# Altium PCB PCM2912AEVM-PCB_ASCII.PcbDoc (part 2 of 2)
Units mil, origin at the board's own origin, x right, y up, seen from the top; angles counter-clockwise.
Board outline 2362.2 x 944.88 mil, 4 copper layers (Top Layer, GND1 Layer, GND2 Layer, Bottom Layer), stack 58.906 mil thick; 73 components, 35 nets, 156 pads, 64 vias.
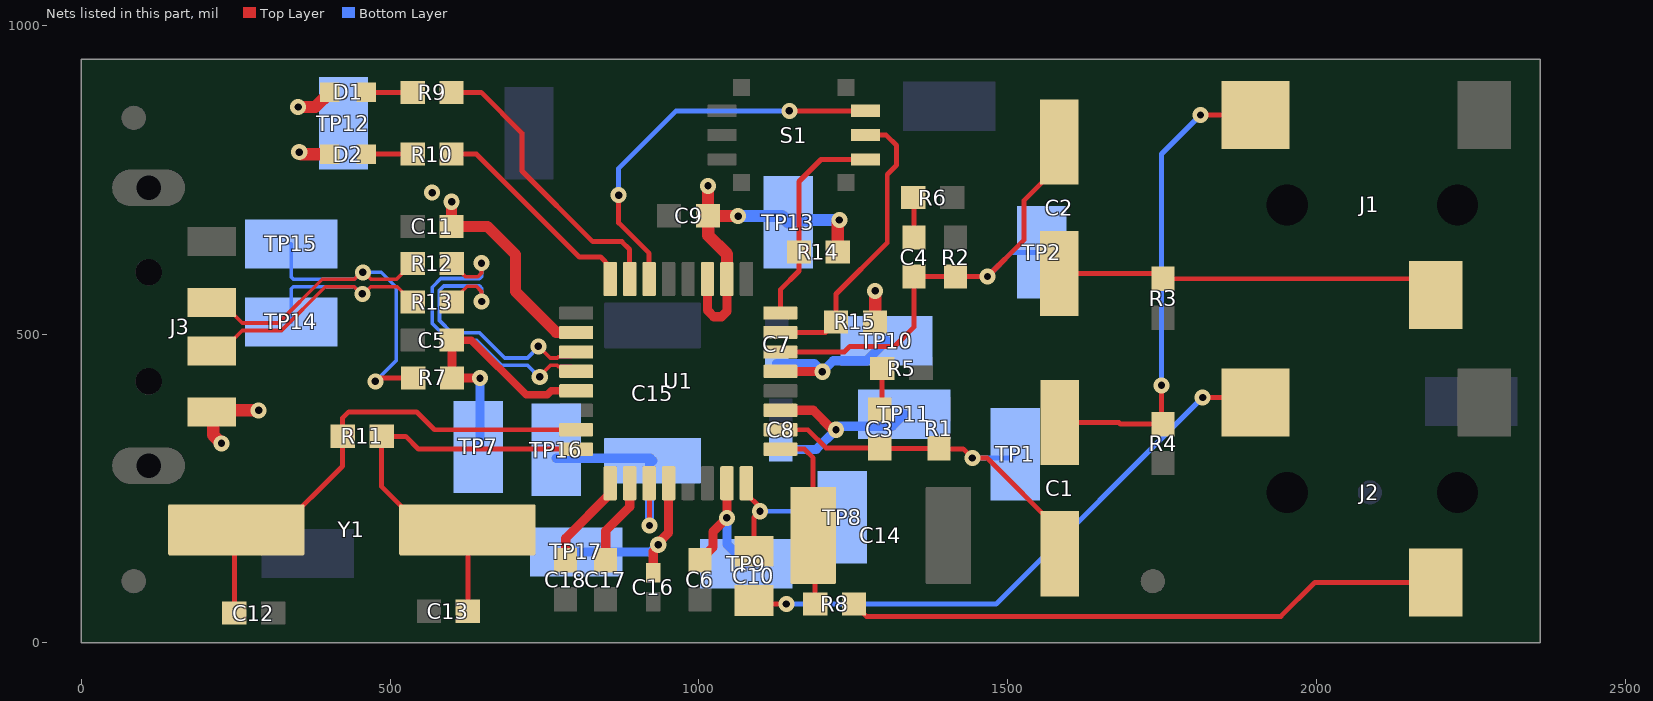
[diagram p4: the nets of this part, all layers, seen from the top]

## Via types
v1: diameter 26, hole 12, Top Layer to Bottom Layer, tented both sides, 64 vias

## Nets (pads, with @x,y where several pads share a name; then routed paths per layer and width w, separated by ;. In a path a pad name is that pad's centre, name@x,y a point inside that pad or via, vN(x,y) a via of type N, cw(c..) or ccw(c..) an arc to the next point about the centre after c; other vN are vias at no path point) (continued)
NetC1_1: C1.1 C3.1 R1.2 TP1.1 U1.18 | length 630.9
  Top Layer w8: U1.18@1132.02,345.06 1176.43,345.06 1205.82,315.67 1292.85,315.67 C3.1@1292.85,314.69 1388.41,314.69 R1.2@1388.75,315.03 1388.75,314.04 1428.07,314.04 v1(1442.77,299.34) 1466.62,299.34 1584.34,181.62 C1.1@1584.34,144.22
  Bottom Layer w8: v1(1442.77,299.34) 1506.27,299.34 TP1.1@1512.33,305.41
NetC1_2: C1.2 J1.2 R4.2 | length 785.7
  Top Layer w8: C1.2@1584.34,356.82 1680,356.82 1682.67,354.15 R4.2@1751.71,354.15 1749.05,356.82 v1(1749.05,416.8) ; v1(1812.19,854.74) J1.2@1901.57,854.74
  Bottom Layer w8: v1(1749.05,416.8) 1749.05,791.59 v1(1812.19,854.74)
NetC2_1: C2.1 C4.1 R2.2 TP2.1 U1.22 | length 803.3
  Top Layer w8: U1.22@1132.02,471.04 1235.53,471.04 1244.41,479.92 1316.72,479.92 1348.57,511.77 C4.1@1348.57,593.24 R2.2@1415.51,593.24 v1(1467.31,593.24) 1526.13,652.06 1526.13,716.07 1583.5,773.43 C2.1@1583.5,810.84
  Bottom Layer w8: v1(1467.31,593.24) 1506.41,632.34 TP2.1@1555.09,632.34
NetC2_2: C2.2 J1.3 R3.2 | length 623.8
  Top Layer w8: C2.2@1583.5,598.24 1742.98,598.24 R3.2@1751.71,589.5 2166.8,589.5 J1.3@2192.91,563.4
NetC3_2: C3.2 R5.2 | length 68
  Top Layer w8: C3.2@1292.85,377.68 1296.7,381.54 R5.2@1296.7,444.06
NetC4_2: C4.2 R6.2 | length 65.4
  Top Layer w8: R6.2@1347.08,721.03 1348.57,719.54 C4.2@1348.57,656.23
NetC5_1: C5.1 R7.2 TP7.1 U1.5 | length 460.7
  Top Layer w8: R7.2@599.79,429.51 R7.2@600.31,428.99 ; C5.1@599.79,490.22 C5.1@600.05,489.96 ; v1@645.29,429.02 v1(645.59,428.72)
  Top Layer w12: C5.1@599.79,490.22 631.65,490.22 720.21,401.67 754.32,401.67 760.71,408.05 U1.5@801.31,408.05
  Top Layer w15: R7.2@599.79,429.51 600.05,429.77 C5.1@600.05,489.96 ; R7.2@600.31,428.99 600.44,428.85 645.12,428.85 v1@645.29,429.02
  Bottom Layer w10: TP7.1@643.02,317.17 TP7.1@645.59,319.74
  Bottom Layer w15: TP7.1@645.59,319.74 v1(645.59,428.72)
NetC6_1: C6.1 TP9.1 U1.15 | length 230.1
  Top Layer w15: C6.1@1001.62,133.66 1022.78,154.83 1022.78,179.87 v1(1045.4,202.49) U1.15@1045.4,258.44
  Bottom Layer w15: v1(1045.4,202.49) 1045.4,159.86 TP9.1@1076.9,128.36
NetC7_1: C7.1 TP10.1 U1.21 | length 272.2
  Top Layer w15: U1.21@1132.02,439.54 1199.42,439.54 v1(1199.97,439)
  Bottom Layer w15: C7.1@1126.07,452.24 1186.72,452.24 v1(1199.97,439) 1217.64,456.68 1271.22,456.68 TP10.1@1303.82,489.27
NetC8_1: C8.1 TP11.1 U1.19 | length 326.8
  Top Layer w15: U1.19@1132.02,376.55 1184.97,376.55 1216.47,345.06 v1(1221.97,345.06)
  Bottom Layer w15: C8.1@1132.57,313.26 1190.17,313.26 v1(1221.97,345.06) 1227.64,350.72 1313.12,350.72 TP11.1@1332.71,370.31
NetC10_1: C10.1 TP8.1 U1.16 | length 260.8
  Top Layer w8: U1.16@1076.9,258.44 1076.9,241.71 1098.99,219.62 v1(1098.99,213.12) 1088.99,203.12 C10.1@1088.99,148.34
  Bottom Layer w8: v1(1098.99,213.12) 1222.64,213.12 TP8.1@1232.39,203.37
NetC10_2: C10.2 J2.2 | length 956.6
  Top Layer w8: C10.2@1088.99,68.34 1094.36,62.97 v1(1141.58,62.97) ; v1(1815.53,397.22) 1893.52,397.22 J2.2@1901.57,389.17
  Bottom Layer w8: v1(1141.58,62.97) 1481.27,62.97 v1(1815.53,397.22)
NetC12_2: C12.2 R11.1 U1.7 Y1.1 | length 823.3
  Top Layer w8: C12.2@247.83,48.04 247.83,179.87 Y1.1@251,183.05 319.9,183.05 423.28,286.43 R11.1@423.28,334.45 423.28,364.22 433.08,374.02 542.83,374.02 571.79,345.06 U1.7@801.31,345.06
NetC13_2: C13.2 R11.2 U1.8 Y1.2 | length 704.1
  Top Layer w8: R11.2@486.28,334.45 486.28,252.89 556.12,183.05 Y1.2@625.02,183.05 625.91,182.16 C13.2@625.91,51.2 ; R11.2@487.26,334.45 525.12,334.45 546.01,313.56 U1.8@801.31,313.56
NetC14_2: C14.2 R8.1 U1.17 | length 296.6
  Top Layer w8: U1.17@1132.02,313.56 1170.92,313.56 1184.97,299.51 C14.2@1184.97,174.18 1188.15,170.99 R8.1@1188.15,62.97
NetC15_2: C15.2 TP16.1 U1.11 | length 333.4
  Top Layer w8: U1.11@919.42,258.44 919.71,258.15 919.71,190.29 v1(920,190)
  Bottom Layer w15: TP16.1@769.07,298.91 921.17,298.91 C15.2@925.08,295 920,289.91 v1(920,190)
NetC16_1: C16.1 TP17.1 U1.12 | length 291.6
  Top Layer w15: C16.1@926.18,113.81 926.18,147.87 934.21,155.89 v1(934.21,158.87) ; v1@932.95,160.12 950.91,178.08 U1.12@950.91,258.44
  Bottom Layer w15: TP17.1@801.61,147.14 922.48,147.14 v1(934.21,158.87)
NetC17_1: C17.1 U1.10 | length 140.9
  Top Layer w15: C17.1@849.07,133.66 849.07,181.56 887.92,220.41 U1.10@887.92,258.44
NetC18_1: C18.1 U1.9 | length 154.7
  Top Layer w15: C18.1@784.21,133.66 784.21,169.5 856.43,241.71 U1.9@856.43,258.44
NetD1_2: D1.2 R9.1 | length 74.9
  Top Layer w8: D1.2@461.68,891.37 R9.1@536.58,891.37
NetD2_2: D2.2 R10.1 | length 74.9
  Top Layer w8: D2.2@461.68,791.37 R10.1@536.58,791.37
NetJ2_3: J2.3 R8.2 | length 972.7
  Top Layer w8: R8.2@1251.15,62.97 1271.11,43 1942.33,43 1997.16,97.83 J2.3@2192.9,97.83
NetJ3_2: J3.2 R13.1 TP14.1 | length 563.4
  Top Layer w6: J3.2@211.33,472.44 227.08,472.44 260.45,505.81 324.24,505.81 395.17,576.74 441.49,576.74 453.22,565 v1(455,565) 457.25,565 468.75,576.5 511.53,576.5 535.81,552.22 R13.1@536.79,552.22
  Bottom Layer w6: TP14.1@339.99,519.54 339.99,573.24 343.5,576.76 428.03,576.76 441.49,576.74 453.22,565 v1(455,565)
NetJ3_3: J3.3 R7.1 R12.1 TP15.1 | length 858.6
  Top Layer w6: J3.3@211.33,551.18 227.08,551.18 260.45,517.81 319.27,517.81 390.2,588.74 442.41,588.74 453.68,600 v1(455.93,600) 457.94,600 469.44,588.5 509.96,588.5 535.76,614.3 R12.1@536.74,614.3
  Top Layer w8: v1(476.04,423.31) 480.37,423.31 486.05,428.99 R7.1@537.31,428.99
  Bottom Layer w6: TP15.1@339.66,645.84 339.99,645.51 339.99,592.27 343.5,588.76 433,588.76 ; 433.02,588.74 442.41,588.74 453.68,600 v1(455.93,600) 485.56,600 509.96,575.6 509.96,457.23 v1(476.04,423.31)
NetR9_2: R9.2 U1.31 | length 477.4
  Top Layer w8: R9.2@599.57,891.37 647.63,891.37 713.68,825.32 713.68,764.08 828.16,649.61 875.19,649.61 887.92,636.88 U1.31@887.92,589.15
NetR10_2: R10.2 U1.32 | length 352.4
  Top Layer w8: R10.2@599.57,791.37 639.84,791.37 806.48,624.74 840.94,624.74 856.43,609.25 U1.32@856.43,589.15
NetR12_2: R12.2 U1.4 | length 525.1
  Top Layer w6: R12.2@599.73,614.3 600.72,614.3 622.23,592.79 642.16,592.79 648.04,598.66 v1(648.04,614.84) ; v1(742.31,430.67) 742.31,432.11 759.49,449.29 770.25,449.29 772.18,447.37 793.48,447.37 U1.4@801.31,439.54
  Bottom Layer w6: v1@648.07,614.82 648.07,593.32 644.55,589.8 582.01,589.8 568.1,575.89 568.1,516.94 594.95,490.09 639.81,490.09 680.56,449.33 722.49,449.33 741.16,430.67 v1(742.31,430.67)
NetR13_2: R13.2 U1.3 | length 487.7
  Top Layer w6: R13.2@599.79,552.22 599.92,552.22 624.96,577.26 639.9,577.26 648.09,569.07 v1(648.09,552.76) ; v1(740,480) 740.78,480 759.49,461.29 770.25,461.29 772.18,463.21 793.48,463.21 U1.3@801.31,471.04
  Bottom Layer w6: v1(648.09,552.76) 648.07,574.29 644.55,577.8 586.98,577.8 580.1,570.92 580.1,521.91 599.92,502.09 644.78,502.09 685.53,461.33 722.49,461.33 740,478.84 v1(740,480)
NetR14_1: R14.1 S1.4 U1.24 | length 348.1
  Top Layer w8: U1.24@1132.02,534.03 1132.02,572.01 1162.07,602.06 R14.1@1162.07,632.76 1162.07,747.07 1197.73,782.73 S1.4@1269.9,782.73
NetR15_1: R15.1 S1.5 U1.23 | length 480.4
  Top Layer w8: U1.23@1132.02,502.54 1204.79,502.54 R15.1@1222.03,519.78 1222.03,564.75 1305,647.73 1305,758.43 1320,773.43 1320,805.48 1303.39,822.1 S1.5@1269.9,822.1
NetS1_6: S1.6 U1.30 | length 638.1
  Top Layer w8: v1(870,725) 870,680.16 919.42,630.74 U1.30@919.42,589.15 ; v1(1146.58,861.47) S1.6@1269.9,861.47
  Bottom Layer w8: v1(870,725) 870,768.37 963.1,861.47 v1(1146.58,861.47)
VBUS: C11.1 D1.1 D2.1 J3.1 TP12.1 U1.2 | length 590.3
  Top Layer w18: v1(599.57,714.2) C11.1@599.57,674.22 657.78,674.22 703,629 703,568.66 769.12,502.54 U1.2@801.31,502.54
  Top Layer w20: J3.1@213.46,374.02 213.46,336.52 v1(227.08,322.89) ; J3.1@213.87,376.55 v1(287,376.55) ; v1(351.24,867.6) 378.85,867.6 D1.1@402.62,891.37 ; v1(352.95,794.49) 356.07,791.37 D2.1@402.62,791.37
  other v1: 568.07,729
VCCP: C9.1 R14.2 R15.2 TP13.1 U1.26 U1.27 | length 627.2
  Top Layer w15: U1.27@1013.91,589.15 1013.91,538.48 1024.19,528.19 1036.61,528.19 1045.4,536.98 U1.26@1045.4,589.15
  Top Layer w20: C9.1@1014.29,691.24 C9.1@1014.67,691.62 C9.1@1015.22,691.07 ; C9.1@1014.75,691.71 v1(1014.75,739.89) ; U1.26@1045.4,589.15 1045.4,629.5 1015.22,659.68 C9.1@1015.22,691.07 ; v1(1063.4,691.07) C9.1@1015.22,691.07 ; R14.2@1225.06,632.76 1225.06,682.21 v1(1227.56,684.72) ; R15.2@1285.02,519.78 1285.28,520.03 v1(1285.28,569.82)
  Bottom Layer w20: v1(1063.4,691.07) 1134.65,691.07 TP13.1@1144.57,681.14 1148.15,684.72 v1(1227.56,684.72)
pads on no net: FID1.1 FID2.1 FID3.1 FID4.1 FID5.1 FID6.1 J1.4 J1.5 J2.4 J2.5 J3.7 J3.8 LBL1.0 S1.M1 S1.M2 S1.M3 S1.M4 U1.14

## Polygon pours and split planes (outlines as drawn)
GND on Bottom Layer "BOTTOM_LAYER_GND_P024" (solid, remove dead copper, pour order 24): 812.13,916.2 840.94,887.39 840.94,771.45 798.5,729 687.91,729 687.91,916.2
VCCP on Bottom Layer "BOTTOM_LAYER_VCCP_P000" (solid, remove dead copper, pour order 0): 1105,655.86 1087.94,672.92 1076.9,672.92 1033.37,672.92 1000,706.29 1000,754.33 1071.4,825.73 1286.89,825.73 1327.39,785.23 1327.39,561.31 1311.01,544.93 1258.89,544.93 1225.81,578 1117,578 1105,590
VBUS on Bottom Layer "Bottom Layer-VBUS" (solid, remove dead copper, pour order 2): 279.74,418 307.5,418 323,402.5 323,349.26 278.74,305 211.71,305 155,361.71 155,641.57 193.49,680.06 193.49,847.49 262.2,916.2 597.6,916.2 633.33,880.47 633.33,698.2 615.19,680.06 565.94,680.06 517,729 253,729 240,716 240,457.74
VBUS on Top Layer "TOP_LAYER_VBUS_P030" (solid, remove dead copper, pour order 30): 550.69,711.32 580,711.32 580,652.06 625.91,652.06 631.65,657.81 631.65,736.81 621.66,746.81 552.93,746.81 546.01,739.89 546.01,716
GND on Top Layer "Top Layer-GND" (solid, pour order 18): 1474.48,250.52 1495,230 1495,90 1463.83,58.83 1380.67,58.83 1359.7,79.8 1359.7,242.94 1367.27,250.52
GND on GND1 Layer "GND1_LAYER_GND_P026" (solid, remove dead copper, pour order 26): 0,944.88 2362.2,944.88 2362.2,0 0,0
GND on GND2 Layer "GND2_LAYER_GND_P028" (solid, remove dead copper, pour order 28): 0,944.88 2362.2,944.88 2362.2,0 0,0

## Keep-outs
Keep-Out Layer:
  text ".Layer_Name" at -604.1,-1449.04 h60

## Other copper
Top Layer:
  text ".Layer_Name" at -604.1,-1449.04 h60
GND1 Layer:
  text ".Layer_Name" at -604.1,-1460 h60
GND2 Layer:
  text ".Layer_Name" at -570,-1450 h60
Bottom Layer:
  text ".Layer_Name" at -604.1,-1449.04 h60

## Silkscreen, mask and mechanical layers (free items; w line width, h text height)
Top Overlay:
  circle w6: c740,545.29 r12
  lines w6: 377.23,741 395.39,741 ; 377.23,841 395.39,841 ; 393.76,930 632.8,930 644.16,918.64 644.16,749.58 434.12,749.58 ; 407.69,741 423.28,741 ; 407.69,841 423.28,841 ; 408.72,727.77 408.72,754.23 ; 408.72,827.77 408.72,854.23 ; 420.78,764.1 448.68,764.1 ; 420.78,818.64 448.68,818.64 ; 420.78,864.1 448.68,864.1 ; 420.78,918.64 448.68,918.64 ; 654.39,818.64 666.35,806.67 666.35,736.81 ; 1454,423.31 1443.31,423.31 1428.07,408.07 ; 1428.07,408.05 1428.07,408.07 ; 395.39,727.77 407.69,740.07 407.69,741.93 395.39,754.23 395.39,727.77 ; 395.39,827.77 395.39,854.23 407.69,841.93 407.69,840.07 395.39,827.77 ; 642.16,652.84 642.16,731.3 781.72,731.3 815.61,697.41 815.61,641.16 803.16,628.71 666.29,628.71 642.16,652.84
  text "REC" at 236.04,872.6 h60
  text "1:MUTE" at 684.48,863.11 h60
  text "2:HI_PWR" at 684.48,812.18 h60
  text "PLAY" at 203.46,773.35 h60
  text "3:PREAMP" at 684.48,755.28 h60
  text ".Layer_Name" at -604.1,-1449.04 h60
Bottom Overlay:
  text "'.PRJ_Number'.PCB_Rev" at 2144.18,300 h90
  text "'.PRJ_Title'" at 2223.78,99 h90
  text ".Layer_Name" at -604.1,-1449.04 h60
Top Paste:
  text ".Layer_Name" at -604.1,-1449.04 h60
Bottom Paste:
  text ".Layer_Name" at -604.1,-1449.04 h60
Top Solder:
  text ".Layer_Name" at -604.1,-1449.04 h60
  text ".Layer_Name" at -604.1,-1449.04 h60
Bottom Solder:
  text ".Layer_Name" at -604.1,-1449.04 h60
Drill Guide:
  text ".Layer_Name" at -604.1,-1449.04 h60
M1 Board Outline:
  the board outline again, w10
  text ".Layer_Name" at -604.1,-1449.04 h60
M2 Board Dimensions:
  rectangle: -1181.1,-865.55 -1056.1,-740.55
  rectangle: -1056.1,-990.55 -681.1,-865.55
  lines w7: -1181.1,-865.55 -181.1,-865.55 ; -1056.1,-990.55 -1056.1,-740.55 ; -931.1,-990.55 -931.1,-740.55 ; -681.1,-990.55 -681.1,-740.55 ; -431.1,-990.55 -431.1,-740.55 ; -1181.1,-990.55 -181.1,-990.55 -181.1,-740.55 -1181.1,-740.55 -1181.1,-990.55
M3 3D STEP Top:
  text ".Layer_Name" at -604.1,-1449.04 h60
M4 3D STEP Bottom:
  text ".Layer_Name" at -604.1,-1449.04 h60
M5 Assembly Top:
  lines w10: -1473.1,-1520.72 5126.9,-1520.72 ; -1473.1,-1317.38 5128.9,-1317.38 ; -1473.1,-1114.05 -1473.1,-1724.05 2531.9,-1724.05 5128.9,-1724.05 5128.9,-1114.05 -1472.6,-1114.05 -1472.6,-1724.05 102.9,-1724.05 ; 991.9,-1724.05 991.9,-1114.05 ; 2258.9,-1317.38 2258.9,-1114.05 ; 3098.9,-1317.38 3098.9,-1114.05 ; 3720.9,-1730.55 3720.9,-1527.72
  text "+" at 1116.27,221 h40
  text "COMPONENTS MARKED 'DNP' SHOULD NOT BE POPULATED." at -27.6,-909.05 h60
  text "ASSEMBLY VARIANT:" at -28.1,-1024.55 h60
  text ".VariantName" at 1007.9,-1024.55 h60
  text "PCB VIEWED FROM TOP SIDE" at -1409.6,-1246.22 h60
  text "BOARD #:" at 1066.9,-1246.22 h60
  text "REV:" at 2456.9,-1246.22 h60
  text ".PCB_Rev" at 2748.4,-1246.22 h60
  text "SVN REV:" at 3294.9,-1246.22 h60
  text ".VersionControl_RevNumber" at 3800.9,-1246.22 h60
  text ".PRJ_Number" at 1516,-1251 h60
  text ".Layer_Name" at -585,-1444 h60
  text "TID #:" at 1066.9,-1449.55 h60
  text ".TID" at 1612.4,-1449.55 h60
  text "PLOT NAME =" at -1409.6,-1654.89 h60
  text ".plot_File_Name" at -604.1,-1654.89 h60
  text "GENERATED    :" at 1068.9,-1654.89 h60
  text ".Print_Date" at 1938.4,-1654.89 h60
  text ".Print_Time" at 2667.4,-1654.89 h60
  text "TEXAS INSTRUMENTS" at 3931.9,-1654.89 h60
M6 Assembly Bottom:
  lines w10: -1473.6,-1317.88 5128.4,-1317.88 ; -1471.6,-1521.22 5128.4,-1521.22 ; -65.6,-1731.05 -65.6,-1528.22 ; 556.4,-1317.88 556.4,-1114.55 ; 1396.4,-1317.88 1396.4,-1114.55 ; 2663.4,-1724.55 2663.4,-1114.55 ; 3552.4,-1724.55 5127.9,-1724.55 5127.9,-1114.55 -1473.6,-1114.55 -1473.6,-1724.55 1123.4,-1724.55 5128.4,-1724.55 5128.4,-1114.55
  text "+" at 916.84,213.12 h30
  text "COMPONENTS MARKED 'DNP' SHOULD NOT BE POPULATED." at 4920.9,-908.55 h60
  text ".VariantName" at 3876.9,-1024.55 h60
  text "ASSEMBLY VARIANT:" at 4915.9,-1024.55 h60
  text ".VersionControl_RevNumber" at -145.6,-1246.72 h60
  text "SVN REV:" at 360.4,-1246.72 h60
  text ".PCB_Rev" at 906.9,-1246.72 h60
  text "REV:" at 1198.4,-1246.72 h60
  text "BOARD #:" at 2588.4,-1246.72 h60
  text "PCB VIEWED FROM BOTTOM SIDE" at 5064.9,-1246.72 h60
  text ".PRJ_Number" at 2118,-1254 h60
  text ".TID" at 2042.9,-1450.05 h60
  text "TID #:" at 2588.4,-1450.05 h60
  text ".Layer_Name" at 4023,-1457 h60
  text "TEXAS INSTRUMENTS" at -276.6,-1655.39 h60
  text ".Print_Time" at 987.9,-1655.39 h60
  text ".Print_Date" at 1716.9,-1655.39 h60
  text "GENERATED    :" at 2586.4,-1655.39 h60
  text ".plot_File_Name" at 4259.4,-1655.39 h60
  text "PLOT NAME =" at 5064.9,-1655.39 h60
M9 Title Sheet:
  lines w10: -1672.6,450.95 -1472.6,450.95 ; -1672.6,2825.95 -1472.6,2825.95 ; -1672.6,5200.95 -1472.6,5200.95 ; 827.4,-1924.05 827.4,-1724.05 ; 827.4,7375.95 827.4,7575.95 ; 3327.4,-1924.05 3327.4,-1724.05 ; 3327.4,7375.95 3327.4,7575.95 ; 5139.9,-1724.05 5139.9,-1114.05 10122.4,-1114.05 ; 5827.4,-1924.05 5827.4,-1724.05 ; 5827.4,7375.95 5827.4,7575.95 ; 8327.4,-1924.05 8327.4,-1724.05 ; 8327.4,7375.95 8327.4,7575.95 ; 10122.4,-1724.05 10122.4,-1114.05 ; 10122.4,-1414.05 13122.4,-1414.05 ; 10122.4,-814.05 13122.4,-814.05 ; 10123.4,-220.05 13123.4,-220.05 ; 10827.4,-1924.05 10827.4,-1724.05 ; 10827.4,7375.95 10827.4,7575.95 ; 11627.4,-1714.05 11627.4,-1114.05 ; 13122.4,-1114.05 10122.4,-1114.05 ; 13122.4,-514.05 10122.4,-514.05 ; 13127.4,-524.05 13127.4,-1724.05 ; 13127.4,280.45 10123.4,280.45 10122.4,280.45 10122.4,-220.05 10122.4,-514.05 ; 13127.4,450.95 13327.4,450.95 ; 13127.4,2825.95 13327.4,2825.95 ; 13127.4,5200.95 13327.4,5200.95 ; 10122.4,-1114.05 10122.4,-514.05 ; 13127.4,-1724.05 13127.4,7375.95 -1472.6,7375.95 -1472.6,-1724.05 13127.4,-1724.05 ; -1672.6,-1924.05 -1672.6,7575.95 13327.4,7575.95 13327.4,-1924.05 -1672.6,-1924.05
  text "1" at -441.27,7445.95 h70
  text "2" at 2054.4,7445.95 h70
  text "3" at 4543.74,7445.95 h70
  text "4" at 7050.41,7445.95 h70
  text "5" at 9549.4,7445.95 h70
  text "6" at 12054.4,7445.95 h70
  text "A" at -1597.6,6302.95 h70
  text "A" at 13202.4,6302.95 h70
  text "B" at -1597.6,3922.95 h70
  text "B" at 13202.4,3922.95 h70
  text "C" at -1597.6,1547.95 h70
  text "C" at 13202.4,1547.95 h70
  text "PROJECT TITLE:" at 10162.4,-313.05 h45
  text ".PRJ_Title" at 10212.4,-446.38 h70
  text "DESIGNED FOR:" at 10162.4,-614.05 h45
  text ".PRJ_Customer" at 10212.4,-754.05 h70
  text "D" at -1597.6,-822.05 h70
  text "D" at 13202.4,-822.05 h70
  text "FILE NAME:" at 10162.4,-914.05 h45
  text ".PCB_File_Name_No_Path" at 10212.4,-1034.05 h70
  text "Texas Instruments (TI) and/or its licensors do not warrant the accuracy or completeness of this specification" at 5192.9,-1195.89 h45
  text "ENGINEER:" at 10162.4,-1204.05 h45
  text "LAYOUT BY:" at 11667.4,-1204.05 h45
  text "or any information contained therein. TI and/or its licensors do not warrant that this design will meet" at 5147.91,-1308.55 h45
  text ".PRJ_Engineer" at 10212.4,-1359.04 h70
  text ".PCB_Layout" at 11717.9,-1359.04 h70
  text "the specifications, will be suitable for your application or fit for any particular purpose, or will operate in" at 5147.91,-1421.22 h45
  text "ALTIUM DESIGNER VERSION:" at 11667.4,-1514.05 h45
  text "an implementation. TI and/or its licensors do not warrant that the design is production worthy. You should" at 5147.91,-1533.89 h45
  text "completely validate and test your design implementation to confirm the system functionality for your application." at 5192.9,-1646.55 h45
  text ".print_Scale" at 10212.4,-1647.38 h70
  text ".Application_BuildNumber" at 11717.9,-1647.38 h70
  text "1" at -441.27,-1854.05 h70
  text "2" at 2054.4,-1854.05 h70
  text "3" at 4543.74,-1854.05 h70
  text "4" at 7050.41,-1854.05 h70
  text "5" at 9549.4,-1854.05 h70
  text "6" at 12054.4,-1854.05 h70
M10 Fab Notes:
  drawing of 189 lines, arcs and shapes, not listed
  text "DESIGN INFORMATION" at 11200.92,5765.62 h60
  text "MIN. TRACK WIDTH:" at 10556.36,5633.5 h60
  text "6" at 11652.6,5633.5 h60
  text "MIL" at 11807.36,5633.5 h60
  text "MIN. CLEARANCE:" at 10556.36,5509.37 h60
  text "0.2" at 11592.6,5509.37 h60
  text "mm" at 11807.36,5509.37 h60
  text "MIN. VIA PAD SIZE:" at 10556.36,5385.24 h60
  text "26" at 11622.61,5385.25 h60
  text "MIL" at 11807.36,5385.24 h60
  text "0.05mm (2MIL)" at 11251.36,5255.35 h60
  text "MINIMUM ANNULAR RING" at 10227.13,5247.12 h60
  text "EXTERNAL" at 11959.36,5247.12 h60
  text "PER" at 10427.13,5137 h60
  text "IPC-D-275 CLASS 2 LEVEL C" at 10647.13,5136.99 h60
  text "MIL, HOLES" at 12135.36,5036.52 h60
  text "+/-" at 11742.9,5027.93 h60
  text "+/-" at 12596.9,5027.93 h60
  text "REGISTRATION TOLERANCES:" at 10227.13,5026.87 h60
  text "METAL" at 11426.9,5026.87 h60
  text "5" at 12003.1,5026.87 h60
  text "3" at 12836.1,5026.87 h60
  text "MIL" at 12952.36,5026.87 h60
  text "HOLE SIZE TOLERANCE (UNLESS OTHERWISE SPECIFIED):" at 10227.13,4928.55 h60
  text "+/-" at 12596.9,4925.68 h60
  text "3" at 12836.1,4924.62 h60
  text "MIL" at 12952.36,4924.62 h60
  text "MATERIAL:" at 10152.36,4786.97 h60
  text "FR-4 High Tg" at 11138.8,4658.44 h60
  text "X" at 10994.36,4650.46 h60
  text "FR-408" at 10573.36,4645.94 h60
  text "OTHER" at 12061.36,4645.94 h60
  text "62 MIL (1.6mm) +/-10%" at 10893.46,4502.91 h60
  text "X" at 10773.36,4500.46 h60
  text "THICKNESS:" at 10227.13,4494.69 h60
  text "OTHER" at 12178.36,4494.69 h60
  text "TOLERANCE:" at 10227.13,4356.37 h60
  text "X" at 11075.36,4356.37 h60
  text "ANSI IPC-6012 TYPE 3 CLASS 2" at 11253.37,4356.37 h60
  text "OTHER +/-" at 11253.36,4212.18 h60
  text "BOW & TWIST:" at 10227.13,4066.99 h60
  text "X" at 11075.36,4066.99 h60
  text "ANSI IPC-6012 TYPE 3 CLASS 2" at 11253.37,4066.99 h60
  text "OTHER +/-" at 11253.36,3920.3 h60
  text "DRILLING:" at 10152.36,3789.68 h60
  text "NC_DRILL FILES" at 11913.36,3684.49 h60
  text "REFERENCE:" at 10227.13,3680.55 h60
  text "X" at 10884.36,3680.46 h60
  text "AS SHOWN" at 11062.36,3680.55 h60
  text "X" at 11785.36,3680.55 h60
  text "OTHER" at 12211.36,3538.3 h60
  text "PTH COPPER THICKNESS:" at 10226.8,3534.77 h60
  text "X" at 11366.04,3534.77 h60
  text "20-30 um" at 11494.03,3534.77 h60
  text "BOARD FINISH:" at 10152.36,3387.17 h60
  text "SILKSCREEN:" at 10307.58,3277.05 h60
  text "X" at 11265.36,3277.05 h60
  text "TOP" at 11382.36,3277.05 h60
  text "X" at 11775.36,3277.05 h60
  text "BOTTOM" at 11893.36,3277.05 h60
  text "SILKSCREEN COLOR:" at 10307.58,3121.86 h60
  text "X" at 11264.36,3121.86 h60
  text "WHITE" at 11382.36,3121.86 h60
  text "OTHER" at 11893.36,3121.86 h60
  text "X" at 11395.36,2978.41 h60
  text "GREEN" at 11513.36,2978.41 h60
  text "OTHER" at 12131.36,2978.41 h60
  text "SOLDER RESIST COLOR:" at 10307.58,2971.54 h60
  text "X" at 11395.36,2824.16 h60
  text "MATTE" at 11513.36,2824.16 h60
  text "SEMI-GLOSS" at 12130.9,2823.52 h60
  text "IMMERSION GOLD (ENIG)" at 11213.36,2651.39 h60
  text "ENEPIG" at 12550.9,2644.17 h60
  text "SURFACE FINISH:" at 10152.36,2643.17 h60
  text "X" at 11035.36,2643.17 h60
  text "IMM. TIN/SILVER OR EQUIV" at 10481.9,2505.85 h60
  text "OTHER" at 11913.36,2501.91 h60
  text "ARRAY/PANEL:" at 10152.36,2346.54 h60
  text "CUT AND TRIM PER M1 BOARD OUTLINE" at 11213.36,2338.31 h60
  text "N.C. ROUTE" at 11213.36,2202.35 h60
  text "X" at 11901.36,2202.35 h60
  text "V. SCORE" at 12079.36,2202.35 h60
  text "CERTIFICATION:" at 10152.36,2073.22 h60
  text "MATERIALS AND WORKMANSHIP FOR ALL PCBS" at 10877.36,2073.22 h60
  text "TO MEET OR EXCEED THE REQUIREMENTS OF:" at 10877.36,1979.16 h60
  text "X" at 10514.87,1850.53 h60
  text "ANSI IPC-A-600F CLASS ->" at 10642.86,1850.53 h60
  text "X" at 12290.87,1850.53 h60
  text "2" at 12400.86,1850.53 h60
  text "1" at 12085.86,1849.03 h60
  text "3" at 12754.86,1849.03 h60
  text "X" at 11326.87,1702.84 h60
  text "RoHS" at 11454.86,1702.84 h60
  text "OTHER" at 12099.26,1702.84 h60
  text "PER ORDER" at 12496.32,1702.84 h60
  text "ALL BOARDS MUST MEET OR EXCEED UL94-V0 REQUIREMENTS." at 10179.9,1549.02 h60
  text "PCB MUST BEAR THE UL94V-0 UL REGISTERED MATERIAL ID NUMBER" at 10179.9,1432.95 h60
  text "*FOR 90 OHMS IMPEDANCE 6 MILS TRACE WIDTH AND 6 MILS SPACING WITH 10 % TOLERANCE." at 3585,1415 h60
  text "IN TOP AND BOTTOM." at 3685,1285 h60
  text "ADDITIONAL REQUIREMENTS:" at 10152.36,1263.53 h60
  text "MICROSECTION:" at 10227.13,1156.4 h60
  text "YES" at 11132.86,1156.4 h60
  text "* ALL VIA'S ARE TENTED." at 3600,1130 h60
  text "REQUIRED" at 11994.36,1012.07 h60
  text "BARE BOARD ELEC. TEST:" at 10227.13,1009.21 h60
  text "NONE" at 11532.86,1009.21 h60
  text "X" at 11876.36,1009.21 h60
  text "PER ORDER" at 12586.36,1009.21 h60
  text "* VENDOR MAY ADJUST SOLDERMASK WHEREVER SOLDERMASK PADS ARE THE SAME SIZE (1:1) AS PER THE MANUFACTURING" at 3579,989 h60
  text "CAPABILITIES AND ALL OTHER SOLDER MASK PADS SHALL NOT BE MODIFIED,PROVIDED NO ADJACENT COPPER IS" at 3712,870 h60
  text "XX MIL VIAS REQUIRE NON-CONDUCTIVE FILL AND PLANARIZE" at 10395.27,804.27 h59
  text "EXPOSED AND NO CONFLICT IS PRODUCED WITH ANY STATED \"VIA TENTING/COVERING\" REQUIREMENTS." at 3648,760 h60
  text "XX MIL VIAS REQUIRE CONDUCTIVE FILL AND PLANARIZE" at 10403.27,700.29 h60
  text "OUTER XX MIL TRACES REQUIRE 50 OHM SINGLE-ENDED IMPEDANCE" at 10402.29,536.91 h58
  text "LAYER 2 & 3 (INNER LAYERS) XX MIL WIDE, XX MIL SPACE / TRACES REQUIRE 100 OHM DIFFERENTIAL IMPEDANCE" at 10394.29,301.19 h60
M11 Gerber Information:
  lines w10: -1473.1,-1520.72 5126.9,-1520.72 ; -1473.1,-1317.38 5128.9,-1317.38 ; -1473.1,-1114.05 -1473.1,-1724.05 2531.9,-1724.05 5128.9,-1724.05 5128.9,-1114.05 -1472.6,-1114.05 -1472.6,-1724.05 102.9,-1724.05 ; 991.9,-1724.05 991.9,-1114.05 ; 2258.9,-1317.38 2258.9,-1114.05 ; 3098.9,-1317.38 3098.9,-1114.05 ; 3720.9,-1730.55 3720.9,-1527.72
  text "ALL ARTWORK VIEWED FROM TOP SIDE" at -1409.6,-1246.22 h60
  text "BOARD #:" at 1066.9,-1246.22 h60
  text "REV:" at 2456.9,-1246.22 h60
  text ".PCB_Rev" at 2748.4,-1246.22 h60
  text "SVN REV:" at 3294.9,-1246.22 h60
  text ".VersionControl_RevNumber" at 3800.9,-1246.22 h60
  text ".PRJ_Number" at 1524,-1260 h60
  text "LAYER NAME =" at -1409.6,-1449.04 h60
  text "TID #:" at 1066.9,-1449.55 h60
  text ".TID" at 1612.4,-1449.55 h60
  text "PLOT NAME =" at -1409.6,-1654.89 h60
  text ".plot_File_Name" at -604.1,-1654.89 h60
  text "GENERATED    :" at 1068.9,-1654.89 h60
  text ".Print_Date" at 1938.4,-1654.89 h60
  text ".Print_Time" at 2667.4,-1654.89 h60
  text "TEXAS INSTRUMENTS" at 3931.9,-1654.89 h60
M12 Stackup:
  drawing of 295 lines, arcs and shapes, not listed
  text "Layer" at 4735.34,6397.5 h60
  text "Name" at 5145.26,6397.5 h60
  text "Material" at 6075,6397.5 h60
  text "Thickness" at 6934.77,6397.5 h60
  text "Constant" at 7584.6,6397.5 h60
  text "Board Layer Stack" at 8154.46,6397.5 h60
  text "Top Overlay" at 5145.26,6277.5 h60
  text "Top Solder" at 5145.26,6157.5 h60
  text "Solder Resist" at 6075,6157.5 h60
  text "2.00mil" at 6934.77,6157.5 h60
  text "3.5" at 7584.6,6157.5 h60
  text "1" at 4735.34,6037.5 h60
  text "Top Layer" at 5145.26,6037.5 h60
  text "Copper" at 6075,6037.5 h60
  text "1.50mil" at 6934.77,6037.5 h60
  text "Dielectric 1" at 5145.26,5917.5 h60
  text "FR-4 HIGH Tg" at 6075,5917.5 h60
  text "4.31mil" at 6934.77,5917.5 h60
  text "4.1" at 7584.6,5917.5 h60
  text "2" at 4735.34,5797.5 h60
  text "GND1 Layer" at 5145.26,5797.5 h60
  text "Copper" at 6075,5797.5 h60
  text "1.40mil" at 6934.77,5797.5 h60
  text "Dielectric 2" at 5145.26,5677.5 h60
  text "FR-4 HIGH Tg" at 6075,5677.5 h60
  text "44.49mil" at 6934.77,5677.5 h60
  text "4.8" at 7584.6,5677.5 h60
  text "3" at 4735.34,5557.5 h60
  text "GND2 Layer" at 5145.26,5557.5 h60
  text "Copper" at 6075,5557.5 h60
  text "1.40mil" at 6934.77,5557.5 h60
  text "Dielectric 3" at 5145.26,5437.5 h60
  text "FR-4 HIGH Tg" at 6075,5437.5 h60
  text "4.31mil" at 6934.77,5437.5 h60
  text "4.1" at 7584.6,5437.5 h60
  text "4" at 4735.34,5317.5 h60
  text "Bottom Layer" at 5145.26,5317.5 h60
  text "Copper" at 6075,5317.5 h60
  text "1.50mil" at 6934.77,5317.5 h60
  text "Bottom Solder" at 5145.26,5197.5 h60
  text "Solder Resist" at 6075,5197.5 h60
  text "2.00mil" at 6934.77,5197.5 h60
  text "3.5" at 7584.6,5197.5 h60
  text "Bottom Overlay" at 5145.26,5077.5 h60
M13 Component Bodies Top:
  text ".Layer_Name" at -604.1,-1449.04 h60
M14 Component Bodies Bottom:
  text ".Layer_Name" at -604.1,-1449.04 h60
M15 Courtyards Top:
  text ".Layer_Name" at -604.1,-1449.04 h60
M16 Courtyards Bottom:
  text ".Layer_Name" at -604.1,-1449.04 h60
Drill Drawing:
  lines w10: 4154.99,2303.19 4210.24,2303.19 4210.24,2358.45 4154.99,2358.45 4154.99,2303.19 ; 4154.99,2441.33 4168.8,2441.33 4182.61,2427.51 4196.43,2441.33 4210.24,2441.33 4196.43,2455.14 4210.24,2468.95 4196.43,2468.95 4182.61,2482.77 4168.8,2468.95 4154.99,2468.95 4168.8,2455.14 4154.99,2441.33 ; 4154.99,2607.09 4210.24,2607.09 4182.61,2551.83 4154.99,2607.09 ; 4154.99,2676.15 4182.61,2689.97 4210.24,2676.15 4196.43,2703.78 4210.24,2731.41 4182.61,2717.59 4154.99,2731.41 4168.8,2703.78 4154.99,2676.15
  lines w12: 4104.9,2265.9 7369.8,2265.9 ; 4104.9,2763.18 7369.8,2763.18 ; 4442.76,2141.58 4442.76,2887.5 ; 4774.76,2141.58 4774.76,2887.5 ; 5411.32,2141.58 5411.32,2887.5 ; 5670.46,2141.58 5670.46,2887.5 ; 6045.62,2141.58 6045.62,2887.5 ; 6769.95,2141.58 6769.95,2887.5 ; 4104.9,2141.58 7369.8,2141.58 7369.8,2887.5 4104.9,2887.5 4104.9,2141.58
  text "Symbol" at 4179.49,2800.47 h72
  text "Quantity" at 4480.06,2800.47 h72
  text "Finished Hole Size" at 4812.06,2800.47 h72
  text "Plated" at 5448.62,2800.47 h72
  text "Hole Type" at 5707.76,2800.47 h72
  text "Drill Layer Pair" at 6082.92,2800.47 h72
  text "Hole Length" at 6807.25,2800.47 h72
  text "64" at 4480.06,2676.15 h60
  text "12.00mil (0.305mm)" at 4812.06,2676.15 h60
  text "PTH" at 5448.62,2676.15 h60
  text "Round" at 5707.76,2676.15 h60
  text "Top Layer - Bottom Layer" at 6082.92,2676.15 h60
  text "-" at 6807.25,2676.15 h60
  text "2" at 4480.06,2551.83 h60
  text "39.37mil (1.000mm)" at 4812.06,2551.83 h60
  text "PTH" at 5448.62,2551.83 h60
  text "Slot" at 5707.76,2551.83 h60
  text "Top Layer - Bottom Layer" at 6082.92,2551.83 h60
  text "98.43mil (2.500mm)" at 6807.25,2551.83 h60
  text "2" at 4480.06,2427.51 h60
  text "43.00mil (1.092mm)" at 4812.06,2427.51 h60
  text "NPTH" at 5448.62,2427.51 h60
  text "Round" at 5707.76,2427.51 h60
  text "Top Layer - Bottom Layer" at 6082.92,2427.51 h60
  text "-" at 6807.25,2427.51 h60
  text "4" at 4480.06,2303.19 h60
  text "66.93mil (1.700mm)" at 4812.06,2303.19 h60
  text "NPTH" at 5448.62,2303.19 h60
  text "Round" at 5707.76,2303.19 h60
  text "Top Layer - Bottom Layer" at 6082.92,2303.19 h60
  text "-" at 6807.25,2303.19 h60
  text "72 Total" at 4480.06,2178.87 h60
  text "Slot definitions :" at 4179.49,2091.85 h60
  text "Routed Path Length" at 4630.21,2091.85 h60
  text "= Calculated from tool start centre position to tool end centre position." at 5169.94,2091.85 h60
  text "Hole Length" at 4630.21,2042.12 h60
  text "= Routed Path Length + Tool Size = Slot length as defined in the PCB layout" at 4970.14,2042.12 h60
  text "TOLERANCE" at 5520,1895 h60
  text "+0/-12 MILS FOR 12 MILS DRILL" at 5250,1775 h60
  text "+/- 3 MILS FOR PTH AND SLOT" at 5255,1655 h60
  text "+/- 2 MILS FOR NPTH" at 5255,1550 h60
  text ".Layer_Name" at -604.1,-1449.04 h60
M17 Embedded Cavity:
  text ".Layer_Name" at -604.1,-1449.04 h60
M18 Embedded Assembly:
  text ".Layer_Name" at -604.1,-1449.04 h60
M19 Embedded Keepout:
  text ".Layer_Name" at -604.1,-1449.04 h60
